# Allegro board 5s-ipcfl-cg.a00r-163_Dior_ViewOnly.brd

Outline 170 x 172.3 mm; copper layers: TOP, GND, IN1, IN2, VCC, BOTTOM. Coordinates in mm from the lower left corner of the outline.
Outline path: 0,171.3 arc(0.29,172.01) 1,172.3 17.66,172.3 17.66,158.82 arc(18.16,158.32) 18.66,158.82 33.56,158.82 arc(34.06,158.32) 34.56,158.82 34.56,172.3 169,172.3 arc(169.71,172.01) 170,171.3 170,13.3 arc(169.71,12.59) 169,12.3 160,12.3 arc(159.29,12.01) 159,11.3 159,9.3 arc(158.71,8.59) 158,8.3 142.76,8.3 arc(141.82,8.21) 140.91,7.94 137.69,6.66 arc(136.78,6.39) 135.84,6.3 110,6.3 arc(109.65,6.45) 109.5,6.8 109.5,7.8 arc(109.35,8.15) 109,8.3 101,8.3 arc(100.65,8.15) 100.5,7.8 100.5,6.8 arc(100.35,6.45) 100,6.3 74.8,6.3 arc(74.45,6.15) 74.3,5.8 74.3,4.8 arc(74.15,4.45) 73.8,4.3 66.3,4.3 arc(65.59,4.01) 65.3,3.3 65.3,1 arc(65.01,0.29) 64.3,0 25.6,0 arc(24.89,0.29) 24.6,1 24.6,4.8 arc(24.31,5.51) 23.6,5.8 20.2,5.8 arc(19.49,6.09) 19.2,6.8 19.2,10.8 arc(18.91,11.51) 18.2,11.8 8,11.8 arc(7.29,11.51) 7,10.8 arc(6.85,10.45) 6.5,10.3 1,10.3 arc(0.29,10.59) 0,11.3 0,171.3

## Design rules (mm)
net group CLK_REQ: nets LAN_CLKREQ#_R LANCLK_REQ_N
net group HDA: nets HDA_SDI0 HDA_SDI0_R
net group SMB: nets SMLI_DATA SMLI_DATA_R
net group ASY: nets H_THMTRIP# H_THMTRIP#_CPU H_TRIGIN PCH_TGR_L900MIL PCH_THMTRIP#_R
net group DP: nets DPC_AUXN DPC_AUXN_C DPC_AUXP DPC_AUXP_C
net group DP_CTRL: nets DPC_CTRL_CLK DPC_CTRL_CLK_R DPC_CTRL_DATA DPC_CTRL_DATA_R
net group SVID: nets VCORE_ALERT VCORE_SCLK VCORE_SDIO VIDALERT# VIDSCLK VIDSOUT
net group USB2.0: nets USB_PN2_F2 USB_PN2_F2_R USB_PP1_F1 USB_PP1_F1_R USB_PP2_F2 USB_PP2_F2_R

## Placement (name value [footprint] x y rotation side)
AC1  22PF/50V  [MX_C0402_SMALL_T01]  18.55 26.92 225 top
AC3  10UF/6.3V  [MX_C0603_SMALL_T01]  20.68 26.84 0 top
AC4  0.1UF/6.3V  [TX_C0201]  20.62 25.8 0 top
AC5  0.1UF/16V  [MX_C0402_SMALL_T01]  23.53 26.69 270 bottom
AC6  0.1UF/25V  [MX_C0402_SMALL_T01]  35.24 110.5 270 bottom
AC12  10UF/6.3V  [MX_C0603_SMALL_T01]  14.82 16.14 270 top
AC13  0.1UF/16V  [MX_C0402_SMALL_T01]  14.88 17.8 180 top
AC14  1UF/16V  [MX_C0603_SMALL_T01]  22.02 18.68 0 top
AC20  10PF/50V  [MX_C0402_SMALL_T01]  25.68 109.97 0 top
AC24  1UF/16V  [MX_C0603_SMALL_T01]  22.03 17.24 0 top
AC25  10PF/50V  [MX_C0402_SMALL_T01]  25.68 109.04 0 top
AC47  10PF/50V  [MX_C0402_SMALL_T01]  5.93 98.11 180 bottom
AC52  10UF/6.3V  [MX_C0603_SMALL_T01]  24.62 26.77 270 bottom
AC53  1UF/6.3V  [MX_C0402_SMALL_T01]  22.93 21.11 90 bottom
AC70  22PF/50V  [MX_C0402_SMALL_T01]  42.31 110.53 90 top
AC82  10UF/6.3V  [MX_C0603_SMALL_T01]  22.09 25.96 90 bottom
AC84  0.1UF/16V  [MX_C0402_SMALL_T01]  7.65 26.96 0 top
AC85  10UF/6.3V  [MX_C0603_SMALL_T01]  11.41 22.09 180 top
AC86  10UF/6.3V  [MX_C0603_SMALL_T01]  16.11 16.23 270 top
AC87  2.2UF/6.3V  [MX_C0603_SMALL_T01]  17.38 16.25 270 top
AC88  10UF/6.3V  [MX_C0603_SMALL_T01]  22.03 18.69 0 bottom
AC89  10UF/6.3V  [MX_C0603_SMALL_T01]  24.05 18.81 270 bottom
AC90  10UF/6.3V  [MX_C0603_SMALL_T01]  24.76 19.42 270 top
AC92  10UF/6.3V  [MX_C0603_SMALL_T01]  24.12 29.95 90 top
AC93  0.1UF/16V  [MX_C0402_SMALL_T01]  23.14 21.43 0 top
AC94  0.1UF/16V  [MX_C0402_SMALL_T01]  24.28 27.24 270 top
AC95  10UF/6.3V  [MX_C0603_SMALL_T01]  23.22 25.02 0 top
AC96  0.1UF/16V  [MX_C0402_SMALL_T01]  23.16 23.1 0 top
AC97  0.1UF/16V  [MX_C0402_SMALL_T01]  12.56 23.34 180 top
AC98  0.1UF/16V  [MX_C0402_SMALL_T01]  12.53 24.25 180 top
AC99  10UF/16V  [MX_C0805_SMALL_T02]  9.04 18 90 top
AC100  10UF/16V  [MX_C0805_SMALL_T02]  11.13 20.44 0 top
AC202  22UF/16V  [MX_C1206_H75]  11.92 18.22 180 top
AC203  22UF/16V  [MX_C1206_H75]  11.92 15.74 180 top
AC204  100PF/50V  [MX_C0402_SMALL_T01]  6.94 25.09 180 top
AC205  0.1UF/16V  [MX_C0402_SMALL_T01]  9.6 25.22 0 top
AC206  0.1UF/16V  [MX_C0402_SMALL_T01]  4.73 27.68 270 top
AC207  47UF/6.3V  [TX_C0805_T02_H57]  110.47 162.81 270 top
AC208  10UF/16V  [MX_C0805_SMALL_T02]  43.86 137.84 0 bottom
AC209  0.1UF/25V  [MX_C0402_SMALL_T01]  44.27 133.47 270 bottom
AMB_Q1  2N3904G-TF  [DX_TO92_102_FSBREC_LF5]  156.33 16.6 0 top
APD1  1N4148WX  [TX_SOD323_79X55_H45]  58.86 47.72 90 top
APD2  1N4148WX  [TX_SOD323_79X55_H45]  58.69 52.12 270 top
APR5  0 Ohm  [MX_R0402_SMALL_T01]  34.77 47.05 135 top
APR6  0 Ohm  [MX_R0402_SMALL_T01]  41.93 55.26 0 bottom
APR7  0 Ohm  [MX_R0402_SMALL_T01]  30.96 43.78 180 bottom
APR8  0 Ohm  [MX_R0402_SMALL_T01]  46.35 55.73 0 bottom
APR9  0 Ohm  [MX_R0402_SMALL_T01]  57.2 53.63 90 bottom
APR10  0 Ohm  [MX_R0402_SMALL_T01]  47.98 55.84 270 bottom
APR17  0Ohm  [MX_R0402_SHORT_SMALL_T01]  11.5 106.44 180 top
APR18  0Ohm  [MX_R0402_SHORT_SMALL_T01]  18.56 104.31 0 top
APR19  0Ohm  [MX_R0402_SHORT_SMALL_T01]  18.86 118.53 90 top
APR29  0Ohm  [MX_R0402_SHORT_SMALL_T01]  45.48 47.77 90 top
APR30  0Ohm  [MX_R0402_SHORT_SMALL_T01]  44.56 47.77 90 top
APR31  0Ohm  [MX_R0402_SHORT_SMALL_T01]  43.64 47.77 90 top
APR46  0  [MX_R0402_SMALL_T01]  6.31 20.14 270 top
APR47  0Ohm  [MX_R0402_SHORT_SMALL_T01]  5.39 20.19 270 top
APR75  0Ohm  [MX_R0402_SHORT_SMALL_T01]  51.61 61.84 180 bottom
APR112  0Ohm  [MX_R0402_SHORT_SMALL_T01]  27.71 109.69 270 top
APR115  0 Ohm  [MX_R0402_SMALL_T01]  58.55 44.49 90 top
APR116  0Ohm  [MX_R0402_SHORT_SMALL_T01]  57.12 44.52 0 top
APR117  0 Ohm  [MX_R0402_SMALL_T01]  7.05 113.23 180 bottom
APR119  0 Ohm  [MX_R0402_SMALL_T01]  18.33 105.26 0 top
APR120  0  [MX_R0402_SMALL_T01]  58.8 57.42 90 top
APR121  0Ohm  [MX_R0402_SHORT_SMALL_T01]  58.95 56 0 top
APR122  0Ohm  [MX_R0402_SHORT_SMALL_T01]  7.05 114.2 0 bottom
APR123  0Ohm  [MX_R0402_SHORT_SMALL_T01]  56.82 47.49 180 top
APR124  0  [MX_R0402_SMALL_T01]  56.82 46.55 180 top
APR125  0 Ohm  [MX_R0402_SMALL_T01]  15.85 104.46 0 top
APR126  0 Ohm  [MX_R0402_SMALL_T01]  15.94 105.39 0 top
APR127  0 Ohm  [MX_R0402_SMALL_T01]  26.44 45.3 90 bottom
APR128  0 Ohm  [MX_R0402_SMALL_T01]  27.38 45.3 90 bottom
APR129  0Ohm  [MX_R0402_SHORT_SMALL_T01]  136.64 41.4 270 bottom
APR130  0 Ohm  [MX_R0402_SMALL_T01]  135.62 41.4 90 bottom
APR131  0 Ohm  [MX_R0402_SMALL_T01]  138.16 42.24 180 bottom
APR132  0  [MX_R0402_SMALL_T01]  50.48 49.88 180 top
APR133  0  [MX_R0402_SMALL_T01]  50.48 48.76 180 top
APR134  0  [MX_R0402_SMALL_T01]  34.26 57.8 0 bottom
APR135  0  [MX_R0402_SMALL_T01]  51.61 60.92 180 bottom
APR136  10K  [MX_R0402_SMALL_T01]  56.83 50.87 0 top
APR137  10K  [MX_R0402_SMALL_T01]  57.11 49.37 180 top
APR142  0  [MX_R0402_SMALL_T01]  13.98 102.42 180 top
APR143  0  [MX_R0402_SMALL_T01]  14.29 103.41 180 top
APR144  0  [MX_R0402_SMALL_T01]  14.25 105.27 90 top
AQ2  NX7002AK  [TX_SOT23_2D4_T01_H43]  31.62 16.14 270 top
AQ3  NX7002AK  [TX_SOT23_2D4_T01_H43]  27.3 16.16 270 top
AQ17  SSM6N15FU  [TX_SOIC_6P_26_87X53_COLY]  106.56 169.27 270 bottom
AQ18  SSM6N15FU  [TX_SOIC_6P_26_87X53_COLY]  109.07 168.9 90 top
AQ19  SSM6N15FU  [TX_SOIC_6P_26_87X53_COLY]  111.54 159.23 90 top
AQ20  SSM6N15FU  [TX_SOIC_6P_26_87X53_COLY]  69.82 138.55 0 top
AR14  75  [MX_R0402_SMALL_T01]  39.28 15.01 270 top
AR15  75  [MX_R0402_SMALL_T01]  43.23 16.58 0 top
AR17  100KOHM  [MX_R0402_SMALL_T01]  32.15 18.71 270 top
AR19  1K  [MX_R0402_SMALL_T01]  26.64 17.63 270 bottom
AR22  18.2 OHM  [MX_R0402_SMALL_T01]  23.56 15.08 0 top
AR23  18.2 OHM  [MX_R0402_SMALL_T01]  24.06 16.35 90 top
AR29  100KOHM  [MX_R0402_SMALL_T01]  27.58 17.63 270 bottom
AR30  70Ohm/100Mhz  [MX_L0603]  166.75 46.14 270 bottom
AR31  70Ohm/100Mhz  [MX_L0603]  164.97 46.09 270 bottom
AR36  0Ohm  [MX_R0603_SHORT_SMALL_T01]  27.18 20.69 180 bottom
AR38  0  [MX_R0603_SMALL_T01]  27.18 19.19 180 bottom
AR40  0  [MX_R0603_SMALL_T01]  22.92 30.02 90 top
AR41  1K  [MX_R0402_SMALL_T01]  82.87 120.77 180 bottom
AR43  1K  [MX_R0402_SMALL_T01]  75.94 117.34 0 top
C1  0.01UF/50V  [MX_C0402_SMALL_T01]  23.44 105.94 270 top
C2  0.01UF/50V  [MX_C0402_SMALL_T01]  22.16 105.94 270 top
C3  0.1UF/16V  [MX_C0402_SMALL_T01]  25.69 111.81 0 top
C4  10UF/6.3V  [MX_C0603_SMALL_T01]  25.72 114.11 0 top
C5  0.01UF/50V  [MX_C0402_SMALL_T01]  25.68 110.89 0 top
C6  0.1UF/16V  [MX_C0402_SMALL_T01]  25.68 108.12 0 top
C7  10UF/6.3V  [MX_C0603_SMALL_T01]  25.72 115.33 0 top
C8  0.01UF/50V  [MX_C0402_SMALL_T01]  4.24 106.44 0 top
C9  0.01UF/50V  [MX_C0402_SMALL_T01]  6.02 106.44 180 top
C10  0.1UF/16V  [MX_C0402_SMALL_T01]  8.3 106.44 0 top
C11  10UF/6.3V  [MX_C0603_SMALL_T01]  25.72 112.89 0 top
C12  180PF/50V  [MX_C0402_SMALL_T01]  15.94 106.33 180 top
C15  120PF/50V  [MX_C0402_SMALL_T01]  33.13 83.07 180 bottom
C16  120PF/50V  [MX_C0402_SMALL_T01]  33.02 83.98 0 bottom
C17  47PF/50V  [MX_C0402_SMALL_T01]  33.29 84.92 0 bottom
C18  120PF/50V  [MX_C0402_SMALL_T01]  33.18 85.87 180 bottom
C45  0.1UF/16V  [MX_C0402_SMALL_T01]  50.87 133.64 0 bottom
C49  1UF/16V  [MX_C0603_SMALL_T01]  20.22 150 180 top
C81  180PF/50V  [MX_C0402_SMALL_T01]  19.76 111.24 90 bottom
C82  180PF/50V  [MX_C0402_SMALL_T01]  20.99 113.5 270 bottom
C83  47PF/50V  [MX_C0402_SMALL_T01]  75.36 140.86 270 bottom
C85  4.7UF/6.3V  [TX_C0402_H24]  25.49 111.66 0 bottom
C86  4.7UF/6.3V  [MX_C0603_SMALL_T01]  36.14 103.16 90 bottom
C94  1000PF/50V  [MX_C0402_SMALL_T01]  112.63 42.29 270 bottom
C97  1UF/16V  [MX_C0603_SMALL_T01]  18.01 148.83 180 top
C98  1UF/16V  [MX_C0603_SMALL_T01]  18.01 147.56 180 top
C178  100uF/16V  [DX_CE_98_268_H236_HD31_LF5]  161.66 78.3 270 top
C200  0.1UF/16V  [MX_C0402_SMALL_T01]  39.57 100.27 0 bottom
C201  10PF/50V  [MX_C0402_SMALL_T01]  73.94 18.1 0 top
C202  10PF/50V  [MX_C0402_SMALL_T01]  82.94 152.82 0 bottom
C204  10PF/50V  [MX_C0402_SMALL_T01]  111.81 162.22 270 top
C205  10PF/50V  [MX_C0402_SMALL_T01]  122.81 141.16 90 top
C206  10PF/50V  [MX_C0402_SMALL_T01]  121.84 141.16 90 top
C207  10PF/50V  [MX_C0402_SMALL_T01]  113.13 142.1 90 top
C248  0.1UF/16V  [MX_C0402_SMALL_T01]  13.94 13.3 180 top
C249  0.1UF/16V  [MX_C0402_SMALL_T01]  16.18 13.53 180 top
C258  1UF/6.3V  [MX_C0402_SMALL_T01]  165.94 50.76 180 bottom
C306  10PF/50V  [MX_C0402_SMALL_T01]  50.87 134.56 0 bottom
C316  10PF/50V  [MX_C0402_SMALL_T01]  30.3 48.5 270 top
C2715  1UF/6.3V  [TX_C0201_T009_H14]  31.76 72.36 45 top
C2726  0.1UF/16V  [MX_C0402_SMALL_T01]  32.36 70.98 270 top
C3101  100PF/50V  [MX_C0402_SMALL_T01]  36.24 168.68 270 top
C3102  100PF/50V  [MX_C0402_SMALL_T01]  16 168.63 270 top
C3907  0.1UF/16V  [MX_C0402_SMALL_T01]  42.26 170.17 90 top
C4000  1UF/6.3V  [TX_C0201_T009_H14]  17.47 144.03 180 top
C4001  0.1UF/16V  [MX_C0402_SMALL_T01]  17.04 137.27 0 top
C4002  0.1UF/16V  [MX_C0402_SMALL_T01]  21.31 137.66 180 top
C4003  4.7UF/6.3V  [MX_C0402_SMALL_T015]  17.52 143.2 180 top
C4004  4.7UF/6.3V  [MX_C0402_SMALL_T015]  15.34 137.15 90 bottom
C4005  4.7UF/6.3V  [MX_C0402_SMALL_T015]  15.34 135.5 270 bottom
C4006  0.1UF/16V  [MX_C0402_SMALL_T01]  19.96 136.08 90 top
C4007  0.1UF/16V  [MX_C0402_SMALL_T01]  18.39 140.43 270 top
C4008  0.1UF/16V  [MX_C0402_SMALL_T01]  17.45 140.43 270 top
C4009  0.1UF/16V  [MX_C0402_SMALL_T01]  19.05 136.01 90 top
C4010  0.1UF/16V  [MX_C0402_SMALL_T01]  21.31 138.67 180 top
C4011  0.1UF/16V  [MX_C0402_SMALL_T01]  20.9 136.08 90 top
C4012  1UF/6.3V  [TX_C0201_T009_H14]  23.39 134.08 0 top
C4013  1UF/16V  [MX_C0603_SMALL_T02_H37]  17.61 138.39 0 top
C4014  0.1UF/16V  [MX_C0402_SMALL_T01]  19.3 140.43 270 top
C4015  0.1UF/16V  [MX_C0402_SMALL_T01]  18.13 136.01 90 top
C4016  4.7UF/6.3V  [MX_C0402_SMALL_T015]  22.17 140.02 270 top
C4017  0.1UF/16V  [MX_C0402_SMALL_T01]  21.22 140.02 270 top
C4018  0.1UF/16V  [MX_C0402_SMALL_T01]  17.14 142.39 270 bottom
C4019  0.1UF/16V  [MX_C0402_SMALL_T01]  18.06 142.39 270 bottom
C4020  0.1UF/16V  [MX_C0402_SMALL_T01]  15.31 142.05 270 bottom
C4021  0.1UF/16V  [MX_C0402_SMALL_T01]  16.23 142.05 270 bottom
C4022  12PF/50V  [MX_C0402_SMALL_T01]  24.74 136.39 90 bottom
C4023  12PF/50V  [MX_C0402_SMALL_T01]  23.85 138.17 270 bottom
C4024  10PF/50V  [MX_C0402_SMALL_T01]  19.05 144.41 90 bottom
C4301  470PF/50V  [MX_C0402_SMALL_T01]  44.37 14.34 0 top
C4302  470PF/50V  [MX_C0402_SMALL_T01]  41.48 13.43 270 top
C4303  680PF/50V  [MX_C0402_SMALL_T01]  31.04 12.54 0 top
C4304  680PF/50V  [MX_C0402_SMALL_T01]  37.37 14.32 180 top
C4305  470PF/50V  [MX_C0402_SMALL_T01]  25.64 14.16 0 top
C4306  470PF/50V  [MX_C0402_SMALL_T01]  33.86 13.58 90 top
C4307  680PF/50V  [MX_C0402_SMALL_T01]  44.88 15.28 0 top
C4308  680PF/50V  [MX_C0402_SMALL_T01]  39.83 16.42 180 top
C4309  680PF/50V  [MX_C0402_SMALL_T01]  33.09 17.58 90 top
C4310  680PF/50V  [MX_C0402_SMALL_T01]  37.02 17.08 0 top
C7201  10UF/6.3V  [MX_C0603_SMALL_T01]  8.41 63.57 270 bottom
C7202  10UF/6.3V  [MX_C0603_SMALL_T01]  16.41 63.39 0 bottom
C7203  10PF/50V  [MX_C0402_SMALL_T01]  9.29 69.64 180 bottom
C7204  0.1UF/16V  [MX_C0402_SMALL_T01]  9.4 68.49 180 bottom
C7205  0.1UF/6.3V  [TX_C0201]  12.04 62.63 0 bottom
C7206  0.1UF/6.3V  [TX_C0201]  18.95 69.43 0 bottom
C7207  0.1UF/6.3V  [TX_C0201]  18.95 70.09 0 bottom
C7208  0.1UF/16V  [MX_C0402_SMALL_T01]  7.14 67.63 180 bottom
C7209  4.7UF/6.3V  [TX_C0402_H24]  15.45 71.97 0 bottom
C7210  0.01UF/50V  [MX_C0402_SMALL_T01]  15.44 71.03 0 bottom
C8301  0.1UF/16V  [MX_C0402_SMALL_T01]  3.21 46.44 270 bottom
C8302  0.1UF/16V  [MX_C0402_SMALL_T01]  4.39 129.05 0 bottom
C8303  0.1UF/16V  [MX_C0402_SMALL_T01]  4.43 72.39 0 bottom
C8304  0.1UF/16V  [MX_C0402_SMALL_T01]  4.6 46.42 270 bottom
C8305  0.1UF/16V  [MX_C0402_SMALL_T01]  89.19 23.4 90 bottom
C8306  0.1UF/16V  [MX_C0402_SMALL_T01]  90.23 23.4 90 bottom
C8307  0.1UF/16V  [MX_C0402_SMALL_T01]  90.92 16.08 270 bottom
C8308  0.1UF/16V  [MX_C0402_SMALL_T01]  75.31 27.73 0 top
C8309  0.1UF/16V  [MX_C0402_SMALL_T01]  125.2 106.01 90 bottom
C8310  0.1UF/16V  [MX_C0402_SMALL_T01]  92.91 76.72 180 bottom
C8311  0.1UF/16V  [MX_C0402_SMALL_T01]  146.91 86.12 0 bottom
C8312  0.1UF/16V  [MX_C0402_SMALL_T01]  116.76 105.98 90 bottom
C8313  0.1UF/16V  [MX_C0402_SMALL_T01]  60.09 105.81 90 bottom
C8314  0.1UF/16V  [MX_C0402_SMALL_T01]  52.22 88.7 270 bottom
C8315  0.1UF/16V  [MX_C0402_SMALL_T01]  54.71 94.63 270 bottom
C8316  10UF/16V  [MX_C0805_SMALL_T02]  54.99 22.72 0 bottom
C9478  1UF/6.3V  [MX_C0402_SMALL_T01]  2.79 148.53 180 bottom
C941488  0.1UF/16V  [MX_C0402_SMALL_T01]  29.74 33.14 270 top
C941489  0.1UF/16V  [MX_C0402_SMALL_T01]  28.98 31.71 0 top
C941490  22UF/6.3V  [MX_C0603_SMALL_T02]  95.36 28.32 90 bottom
C941491  22UF/6.3V  [MX_C0603_SMALL_T02]  96.68 28.32 90 bottom
C941492  10PF/50V  [MX_C0402_SMALL_T01]  7.62 20.41 180 top
C941623  22UF/6.3V  [MX_C0603_SMALL_T02]  157.14 168.39 0 top
C941625  0.1UF/16V  [MX_C0402_SMALL_T01]  132.94 166.49 180 top
C941629  1UF/25V  [MX_C0603_SMALL_T01]  156.87 170.68 0 top
C941631  22UF/6.3V  [MX_C0603_SMALL_T02]  113.02 117.98 0 bottom
C941632  22UF/6.3V  [MX_C0603_SMALL_T02]  113.04 116.66 0 bottom
C941633  22UF/6.3V  [MX_C0603_SMALL_T02]  114.66 115.82 0 top
C941634  22UF/6.3V  [MX_C0603_SMALL_T02]  114.66 114.42 0 top
C941635  0.1UF/16V  [MX_C0402_SMALL_T01]  65.21 44.52 180 bottom
C941636  0.1UF/16V  [MX_C0402_SMALL_T01]  66.27 48.17 0 top
C941643  4.7UF/6.3V  [MX_C0603_SMALL_T01]  42.77 98.3 180 bottom
C941644  4.7UF/6.3V  [MX_C0603_SMALL_T01]  49.08 95.16 90 bottom
C941645  22UF/6.3V  [MX_C0603_SMALL_T02]  104.65 166.89 0 top
C941646  10PF/50V  [MX_C0402_SMALL_T01]  71.93 17.1 180 top
C941647  10PF/50V  [MX_C0402_SMALL_T01]  49.76 17.01 180 top
C941648  0.47UF/16V  [TX_C0603_T015_H37]  30.78 38.24 180 top
C941649  0.47UF/16V  [TX_C0603_T015_H37]  29.08 23.84 180 top
CB171  10UF/25V  [MX_C0805_SMALL_T02]  161.29 72.89 180 top
CB4132  1000PF/50V  [MX_C0402_SMALL_T01]  131.33 61.68 0 bottom
CB4133  0.1UF/16V  [MX_C0402_SMALL_T01]  48.11 72.31 0 top
CB4134  0.1UF/16V  [MX_C0402_SMALL_T01]  48.11 73.23 0 top
CB4135  0.1UF/16V  [MX_C0402_SMALL_T01]  87.11 125.83 180 bottom
CB4152  0.1UF/16V  [MX_C0402_SMALL_T01]  2.84 131.33 180 top
CM3101  90Ohm/100Mhz  [MX_CHOKE_4P_79X47_FUK_COLAY]  7.88 126.39 270 top
CM3102  90Ohm/100Mhz  [MX_CHOKE_4P_79X47_FUK_COLAY]  10.12 127 270 top
CM3103  90Ohm/100Mhz  [MX_CHOKE_4P_79X47_FUK_COLAY]  12.35 127 270 top
CM3104  90Ohm/100Mhz  [MX_CHOKE_4P_79X47_FUK_COLAY]  14.61 127 270 top
CM3301  12ohm  [TX_CHOKE_4P_35X28_PAN]  78.08 20.31 0 top
CM3302  12ohm  [TX_CHOKE_4P_35X28_PAN]  79.86 20.31 0 top
CM3303  90ohm  [MX_CHOKE_4P_55X47_CHI]  69.45 18.54 270 top
CM3601  12ohm  [TX_CHOKE_4P_35X28_PAN]  69.78 148.8 0 bottom
CM3602  12ohm  [TX_CHOKE_4P_35X28_PAN]  71.66 148.21 0 bottom
CM3603  90ohm  [MX_CHOKE_4P_55X47_CHI]  62.36 161.56 90 top
CM3604  90ohm  [MX_CHOKE_4P_55X47_CHI]  60.81 161.55 90 top
CM3605  12ohm  [TX_CHOKE_4P_35X28_PAN]  70.04 150.84 180 top
CM3606  12ohm  [TX_CHOKE_4P_35X28_PAN]  71.9 150.9 180 top
CM3703  90ohm  [MX_CHOKE_4P_55X47_CHI]  40.72 153.73 90 top
CM3704  90ohm  [MX_CHOKE_4P_55X47_CHI]  42.25 153.73 90 top
CM4003  90ohm  [MX_CHOKE_4P_55X47_CHI]  67.8 18.55 270 top
CM4004  12ohm  [TX_CHOKE_4P_35X28_PAN]  63.47 20.28 0 top
CM4005  12ohm  [TX_CHOKE_4P_35X28_PAN]  65.12 20.18 0 top
CR1  GREEN  [MX_LED_2P_63X31_H16]  167.14 23.21 180 top
CR2  GREEN  [MX_LED_2P_63X31_H16]  167.14 24.74 180 top
CR4  CR6  [MX_LED_2P_63X31_EVER]  167.14 30.81 180 top
CR5  GREEN  [MX_LED_2P_63X31_H16]  167.14 29.28 180 top
CR6  GREEN  [MX_LED_2P_63X31_H16]  167.14 27.76 180 top
CR7  GREEN  [MX_LED_2P_63X31_H16]  167.14 32.33 180 top
CR15  WHITE  [DX_LED_D_2P_90_1H_RA_CO_LF5]  21.75 9.1 0 top
CR22  GREEN  [MX_LED_2P_63X31_H16]  167.14 26.26 180 top
CR23  GREEN  [MX_LED_2P_63X31_H16]  167.12 34.29 180 top
D3  BAT54CW  [MX_SOT323]  23.94 148.59 270 top
D4C1  10PF/50V  [MX_C0402_SMALL_T01]  85.18 67.33 180 top
D4C2  1UF/6.3V  [TX_C0201_T009_H14]  85.18 66.37 180 top
D4C3  1UF/6.3V  [TX_C0201_T009_H14]  85.18 65.06 180 top
D4C4  1UF/6.3V  [TX_C0201_T009_H14]  88.48 72.31 90 top
D4C5  0.1UF/16V  [MX_C0402_SMALL_T01]  132.6 61.26 270 bottom
D4C6  2.2UF/6.3V  [MX_C0603_SMALL_T01]  90.06 73.17 180 top
D4C7  0.1UF/16V  [MX_C0402_SMALL_T01]  92.57 72.01 0 top
D4C8  10PF/50V  [MX_C0402_SMALL_T01]  90.31 72.01 180 top
D4C9  0.1UF/6.3V  [MX_C0201]  120.57 59.15 90 bottom
D4C10  22UF/6.3V  [MX_C0603_SMALL_T02]  114.56 62.28 0 bottom
D4C11  0.1UF/16V  [MX_C0402_SMALL_T01]  114.31 63.4 0 bottom
D4C12  10PF/50V  [MX_C0402_SMALL_T01]  92.77 49.53 0 bottom
D4C13  1UF/6.3V  [TX_C0201_T009_H14]  92.26 46.99 0 bottom
D4C14  1UF/6.3V  [TX_C0201_T009_H14]  92.77 48.59 0 bottom
D4C15  1UF/6.3V  [TX_C0201_T009_H14]  91.68 57.27 90 bottom
D4C16  0.1UF/16V  [MX_C0402_SMALL_T01]  131.75 46.9 0 bottom
D4C17  2.2UF/6.3V  [MX_C0603_SMALL_T01]  93.61 60.69 0 bottom
D4C18  0.1UF/16V  [MX_C0402_SMALL_T01]  93 61.76 0 bottom
D4C19  10PF/50V  [MX_C0402_SMALL_T01]  93.3 65.78 0 bottom
D4C20  0.1UF/6.3V  [MX_C0201]  120.51 49.62 0 bottom
D4C21  22UF/6.3V  [MX_C0603_SMALL_T02]  115.19 48.99 270 bottom
D4C22  0.1UF/16V  [MX_C0402_SMALL_T01]  117.27 48.88 270 bottom
D4C23  1UF/6.3V  [MX_C0402_SMALL_T01]  114.31 64.39 180 bottom
D4C24  1UF/6.3V  [MX_C0402_SMALL_T01]  116.33 48.88 90 bottom
D4C25  0.1UF/16V  [MX_C0402_SMALL_T01]  118.21 48.88 270 bottom
D4C26  10PF/50V  [MX_C0402_SMALL_T01]  127.82 69.8 0 bottom
D4C27  10PF/50V  [MX_C0402_SMALL_T01]  117.07 57.7 270 bottom
D4C28  10PF/50V  [MX_C0402_SMALL_T01]  63.68 151.27 0 bottom
D4C29  10PF/50V  [MX_C0402_SMALL_T01]  43.2 170.17 90 top
D4C31  10PF/50V  [MX_C0402_SMALL_T01]  119.02 72.56 90 top
D4C32  10PF/50V  [MX_C0402_SMALL_T01]  132.26 49.7 180 bottom
D4C33  0.1UF/16V  [MX_C0402_SMALL_T01]  120.51 47.79 0 bottom
D4C34  0.1UF/16V  [MX_C0402_SMALL_T01]  114.4 59.81 270 bottom
D4CB1  0.1UF/6.3V  [MX_C0201]  117.7 72.13 180 top
D4CB2  0.1UF/6.3V  [MX_C0201]  128.01 72.22 90 top
D4CB3  0.1UF/6.3V  [MX_C0201]  123.21 72.3 180 top
D4CB4  0.1UF/6.3V  [MX_C0201]  130.37 72.21 90 top
D4CB5  0.1UF/6.3V  [MX_C0201]  120.62 66.28 270 bottom
D4CB6  0.1UF/6.3V  [MX_C0201]  109.27 57.22 270 bottom
D4CB7  0.1UF/6.3V  [MX_C0201]  111.12 61.39 90 bottom
D4CB8  0.1UF/6.3V  [MX_C0201]  143.74 60.57 180 bottom
D4CB9  0.1UF/6.3V  [MX_C0201]  112.13 48.89 270 bottom
D4CB10  0.1UF/6.3V  [MX_C0201]  107.23 58.25 90 bottom
D4CB11  0.1UF/6.3V  [MX_C0201]  134.59 49.44 90 bottom
D4CB12  0.1UF/6.3V  [MX_C0201]  127.54 57.1 270 bottom
D4CB13  0.1UF/6.3V  [MX_C0201]  139.04 57.29 90 bottom
D4CB14  0.1UF/6.3V  [MX_C0201]  126.49 59.5 90 bottom
D4CB15  0.1UF/6.3V  [MX_C0201]  121.65 59.15 90 bottom
D4CB16  10PF/50V  [MX_C0402_SMALL_T01]  145.13 49.15 90 bottom
D4CB17  22UF/6.3V  [MX_C0603_SMALL_T02]  100.29 60.68 180 bottom
D4CB18  22UF/6.3V  [MX_C0603_SMALL_T02]  95.03 69.31 180 bottom
D4CB19  22UF/6.3V  [MX_C0603_SMALL_T02]  155.34 61.25 270 bottom
D4CB20  22UF/6.3V  [MX_C0603_SMALL_T02]  150.11 66.56 90 bottom
D4CB21  22UF/6.3V  [MX_C0603_SMALL_T02]  154.13 47.74 270 bottom
D4CB22  22UF/6.3V  [MX_C0603_SMALL_T02]  96.8 57.67 0 bottom
D4CB23  22UF/6.3V  [MX_C0603_SMALL_T02]  100.3 49.4 180 bottom
D4CB24  22UF/6.3V  [MX_C0603_SMALL_T02]  149.66 56.78 270 bottom
D4CE1  220UF/2V  [MX_C7343D_H79]  118.21 74.64 0 bottom
D4CE2  220UF/2V  [MX_C7343D_H79]  126.32 48.61 180 bottom
D4R2  240  [MX_R0402_SMALL_T01]  124.57 61.08 270 bottom
D4R5  0  [MX_R0402_SMALL_T01]  85.18 70.49 0 top
D4R6  0  [MX_R0402_SMALL_T01]  85.18 69.57 0 top
D4R7  0  [MX_R0402_SMALL_T01]  112.18 61.31 90 bottom
D4R8  1K  [MX_R0402_SMALL_T01]  116.54 60.61 180 bottom
D4R9  1K  [MX_R0402_SMALL_T01]  116.54 61.53 0 bottom
D4R10  0Ohm  [MX_R0402_SHORT_SMALL_T01]  85.18 71.41 180 top
D4R11  0Ohm  [MX_R0402_SHORT_SMALL_T01]  85.18 68.63 180 top
D4R12  0Ohm  [MX_R0402_SHORT_SMALL_T01]  112.52 65.06 90 bottom
D4R14  240  [MX_R0402_SMALL_T01]  123.87 51.99 0 bottom
D4R16  0  [MX_R0402_SMALL_T01]  92.18 51.96 270 bottom
D4R17  0Ohm  [MX_R0402_SHORT_SMALL_T01]  90.64 51.56 270 bottom
D4R18  0  [MX_R0402_SMALL_T01]  113.14 48.8 90 bottom
D4R19  1K  [MX_R0402_SMALL_T01]  120.51 48.7 180 bottom
D4R20  1K  [MX_R0402_SMALL_T01]  120.51 46.75 0 bottom
D4R21  0Ohm  [MX_R0402_SHORT_SMALL_T01]  91.34 49.25 270 bottom
D4R22  0  [MX_R0402_SMALL_T01]  90.42 49.25 270 bottom
D4R23  0Ohm  [MX_R0402_SHORT_SMALL_T01]  114.07 48.8 270 bottom
D4T1  TPC26T  [MX_TPC26T_S4_68]  114.3 71.8 0 top
D4T2  TPC26T  [MX_TPC26T_S4_68]  116.94 63.11 180 bottom
D4T3  TPC26T  [MX_TPC26T_S4_68]  114.68 53.15 180 bottom
D4T4  TPC26T  [MX_TPC26T_S4_68]  114.65 51.4 180 bottom
D519  AZ5125-01J  [MX_S0402_AMAZ_COLAY_T01]  7.31 14.59 0 top
D521  BAV99W-L  [MX_SOT323]  108.02 38.97 270 bottom
D522  BAT54CW  [MX_SOT323]  33.14 47.74 90 bottom
D524  BAT54AW  [MX_SOT323]  68.05 53.3 90 top
D525  BAT54CW  [MX_SOT323]  24.4 151.52 0 top
D3101  AZ3133-08F_R7G  [MX_DFN_10P_118X79_3PAD]  13.67 131.28 180 top
D3102  AZ3133-08F_R7G  [MX_DFN_10P_118X79_3PAD]  9.56 131.28 180 top
D3103  AZ5125-01J  [MX_S0402_AMAZ_COLAY_T01]  35.34 156.59 90 top
D3104  AZ5125-01J  [MX_S0402_AMAZ_COLAY_T01]  36.85 163.97 0 top
D3105  AZ5125-01J  [MX_S0402_AMAZ_COLAY_T01]  16.62 146.79 0 bottom
D3106  AZ5125-01J  [MX_S0402_AMAZ_COLAY_T01]  18.46 150.56 270 top
D3301  IP4284CZ10-TB  [MX_ESD_10P_20_98X39_NXP]  78.98 18.16 0 top
D3302  CM1213_04SO  [MX_SOT23_S6]  68.71 14.85 180 top
D3601  IP4284CZ10-TB  [MX_ESD_10P_20_98X39_NXP]  71.09 150.87 0 bottom
D3602  CM1213_04SO  [MX_SOT23_S6]  61.49 167.68 180 top
D3603  IP4284CZ10-TB  [MX_ESD_10P_20_98X39_NXP]  71.09 153.53 0 top
D3702  CM1213_04SO  [MX_SOT23_S6]  41.63 157.47 0 top
D4003  IP4284CZ10-TB  [MX_ESD_10P_20_98X39_NXP]  64.36 18.07 0 top
D4301  AZ5125-01J  [MX_S0402_AMAZ_COLAY]  44.63 13.25 180 top
D4302  AZ5125-01J  [MX_S0402_AMAZ_COLAY]  39.93 13.25 0 top
D4303  AZ5125-01J  [MX_S0402_AMAZ_COLAY]  35.41 13.6 90 top
D4304  AZ5125-01J  [MX_S0402_AMAZ_COLAY]  29.27 13.57 270 top
D4305  AZ5125-01J  [MX_S0402_AMAZ_COLAY]  37.32 13.28 0 top
D4306  AZ5125-01J  [MX_S0402_AMAZ_COLAY]  25.53 13.08 180 top
D4307  AZ5125-01J  [MX_S0402_AMAZ_COLAY]  32.76 13.35 270 top
D4308  AZ5125-01J  [MX_S0402_AMAZ_COLAY]  27.61 13.08 180 top
D4309  BAT54CW  [MX_SOT323]  29.38 47.35 90 bottom
D4310  AZ5125-01J  [MX_S0402_AMAZ_COLAY_T01]  150.47 157.57 0 top
D5501  AZ5125-01J  [MX_S0402_AMAZ_COLAY]  4.33 23.31 270 bottom
D5502  AZ5125-01J  [MX_S0402_AMAZ_COLAY]  1.67 24.4 90 bottom
D5503  AZ5125-01J  [MX_S0402_AMAZ_COLAY]  2.91 23.28 270 bottom
D6301  TVM1G260M111R  [A_VARISTOR_0603_71X39_TK]  166.9 159.91 0 top
DIMM1  DDR4_SO_260P  [MX_DDR4_260P_20_4HOD_FOX]  124.51 53.18 180 top
DIMM2  DDR4_SO_260P  [MX_DDR4_260P_20_4H_STD_FX]  124.5 65.18 180 top
E16  HEADER_2X5P_K4  [MX_HD_2X5P_79_K4_H248_LF5]  41.25 68.21 90 top
E61  SOCKET_16P  [MX_SOCKET_16P_50_LOTE]  56.44 70.81 270 top
ECR67  0Ohm  [MX_R0402_SHORT_SMALL_T01]  24.93 113.51 270 bottom
ECR73  0Ohm  [MX_R0402_SHORT_SMALL_T01]  25.88 72.48 90 bottom
ECR74  0Ohm  [MX_R0402_SHORT_SMALL_T01]  26.85 72.48 90 bottom
ECR75  0Ohm  [MX_R0402_SHORT_SMALL_T01]  23.93 72.53 90 bottom
ECR76  0Ohm  [MX_R0402_SHORT_SMALL_T01]  24.92 72.48 90 bottom
ECR77  0Ohm  [MX_R0402_SHORT_SMALL_T01]  26.93 91.56 90 top
ECR96  0Ohm  [MX_R0402_SHORT_SMALL_T01]  8.29 95.47 0 top
ECR103  22  [MX_R0402_SMALL_T01]  31.75 89.74 0 bottom
ECR104  0Ohm  [MX_R0402_SHORT_SMALL_T01]  20.45 86.98 90 bottom
ECR106  0  [MX_R0402_SMALL_T01]  26.92 89.93 270 top
ECR107  0  [MX_R0402_SMALL_T01]  24.92 70.6 90 bottom
ECR108  0  [MX_R0402_SMALL_T01]  23.93 70.6 90 bottom
ECR109  0  [MX_R0402_SMALL_T01]  26.85 70.63 90 bottom
ECR110  0  [MX_R0402_SMALL_T01]  25.88 70.6 90 bottom
ECR129  0Ohm  [MX_R0402_SHORT_SMALL_T01]  5.93 101.8 180 bottom
ECR130  0Ohm  [MX_R0402_SHORT_SMALL_T01]  5.93 102.71 180 bottom
ECR131  0Ohm  [MX_R0402_SHORT_SMALL_T01]  6.05 103.63 180 bottom
ECR132  0Ohm  [MX_R0402_SHORT_SMALL_T01]  6.04 105.46 180 bottom
ECR135  0  [MX_R0402_SMALL_T01]  21.94 73.01 0 top
ECR136  0Ohm  [MX_R0402_SHORT_SMALL_T01]  5.93 99.97 180 bottom
ECR137  0Ohm  [MX_R0402_SHORT_SMALL_T01]  5.93 100.89 180 bottom
ECR138  0Ohm  [MX_R0402_SHORT_SMALL_T01]  7.11 89.19 270 top
ECR139  0Ohm  [MX_R0402_SHORT_SMALL_T01]  5.88 89.22 270 top
ECR141  0  [MX_R0402_SMALL_T01]  17.92 118.53 90 top
ECR142  0  [MX_R0402_SMALL_T01]  29.31 103.42 180 bottom
ECR143  0Ohm  [MX_R0402_SHORT_SMALL_T01]  29.31 102.56 180 bottom
ECR144  0Ohm  [MX_R0402_SHORT_SMALL_T01]  29.06 97.5 180 bottom
ECR145  0Ohm  [MX_R0402_SHORT_SMALL_T01]  29.89 96.59 180 bottom
ECR146  0  [MX_R0402_SMALL_T01]  18.01 101.72 180 top
ECR147  0Ohm  [MX_R0402_SHORT_SMALL_T01]  6.92 98.88 180 top
ECR148  0Ohm  [MX_R0402_SHORT_SMALL_T01]  20.05 113.5 270 bottom
ECR149  0Ohm  [MX_R0402_SHORT_SMALL_T01]  23.97 113.51 270 bottom
ECR154  0Ohm  [MX_R0402_SHORT_SMALL_T01]  44.12 40.48 90 top
ECR155  0Ohm  [MX_R0402_SHORT_SMALL_T01]  99.9 12.46 180 bottom
ECR156  0Ohm  [MX_R0402_SMALL_T01]  97.89 8.14 90 top
ECR157  0Ohm  [MX_R0402_SMALL_T01]  99.63 10.02 180 top
ECR159  0  [MX_R0402_SMALL_T01]  41.48 137.63 270 bottom
ECR160  0  [MX_R0402_SMALL_T01]  41.48 136.01 90 bottom
F1  SMD0805P050TF  [TX_POLYSWITCH_2P_87X59_H49]  153.62 165.22 270 top
F3R1  20K  [MX_R0402_SMALL_T01]  64.57 68.54 0 top
F3R2  20K  [MX_R0402_SMALL_T01]  46.23 70.63 90 top
F3R6  0  [MX_R0402_SMALL_T01]  44.68 65.17 180 top
F3R7  33 OHM  [MX_R0402_SMALL_T01]  47.98 66.92 0 top
F3R8  33 OHM  [MX_R0402_SMALL_T01]  48.21 65.95 0 top
F3R9  33 OHM  [MX_R0402_SMALL_T01]  64.54 66.59 180 top
F3R10  33 OHM  [MX_R0402_SMALL_T01]  65.25 72.38 180 top
F3R11  33 OHM  [MX_R0402_SMALL_T01]  64.72 71.36 0 top
F3R12  33 OHM  [MX_R0402_SMALL_T01]  47.55 70.53 0 top
F3R20  0Ohm  [MX_R0402_SHORT_SMALL_T01]  44.68 67.22 180 top
F3R21  0Ohm  [MX_R0402_SHORT_SMALL_T01]  44.68 69.59 180 top
F3R22  0 Ohm  [MX_R0402_SMALL_T01]  64.57 67.6 180 top
F3R23  1.5K  [MX_R0402_SMALL_T01]  65.63 73.4 180 top
F3R24  0Ohm  [MX_R0402_SHORT_SMALL_T01]  44.68 66.23 180 top
F3R25  0Ohm  [MX_R0402_SHORT_SMALL_T01]  44.68 68.19 180 top
F3R26  0Ohm  [MX_R0402_SHORT_SMALL_T01]  44.68 70.5 180 top
F3R27  0Ohm  [MX_R0402_SHORT_SMALL_T01]  44.68 64.2 180 top
F3R28  0Ohm  [MX_R0402_SHORT_SMALL_T01]  52.02 108.96 0 top
F3R29  0Ohm  [MX_R0402_SHORT_SMALL_T01]  39.11 76.39 180 top
F3R70  0  [MX_R0402_SMALL_T01]  17.55 67.59 0 bottom
F3R71  2.2K  [MX_R0402_SMALL_T01]  66.66 64.79 270 top
FCB1  10PF/50V  [MX_C0402_SMALL_T01]  167.11 75.91 0 top
FCB2  10PF/50V  [MX_C0402_SMALL_T01]  160.09 71.06 90 bottom
FD1  BAT54CW  [MX_SOT323]  160.08 68.25 270 bottom
FR1  4.7KOHM  [MX_R0402_SMALL_T01]  167.06 78.09 0 top
FR2  150 OHM  [MX_R0603_SMALL_T01]  167.09 77 0 top
FR10  8.2K  [MX_R0402_SMALL_T01]  6.92 99.84 0 top
FR12  8.2K  [MX_R0402_SMALL_T01]  125.7 158.23 90 top
H1  C315D181N  [HOLE_C315D181N_M2_P2_V8]  79.86 132.98 0 top
H2  C275D177N  [HOLE_C275D177N_M2_P2_V8]  43.95 26.3 180 top
H3  C334D157N  [HOLE_C334D157N_M2_P2_V8]  156.94 155.49 0 top
H4  C275D177N  [HOLE_C275D177N_M2_P2_V8]  12.95 32.23 0 top
H5  C315D181N  [HOLE_C315D181N_M2_P2_V8#2]  165.86 132.98 0 top
H6  C334D157N  [HOLE_C334D157N_M2_P2_V8]  6.35 138.98 0 top
H7  C275D177N  [HOLE_C275D177N_M2_P2_V8]  12.95 82.23 0 top
H8  C334D157N  [HOLE_C334D157N_M2_P2_V8]  165 17.3 0 top
H9  C394D157N  [HOLE_C394D157N_M2_P2_V8_SPE]  80.5 47.28 0 top
H10  D169N_D98x197N  [H_2D_D169ND98X197N_M2_P2_V7]  79.86 90.98 0 top
H11  C315D169N  [HOLE_C315D169N_M2_P2_V8]  165.86 90.98 0 top
H12  C157D157N  [HOLE_C157D157N]  91 10.3 0 top
H13  CT217B63D47  [MX_SMT_NUT_CT217B63D47_NSP]  29.45 42.25 0 top
H14  CT217B63D47  [MX_SMT_NUT_CT217B63D47_NSP]  58.45 40.25 0 top
H15  O118X28DO118X28N  [A_HOLE_O118X28DO118X28N]  61.44 49.16 90 top
H16  O118X28DO118X28N  [A_HOLE_O118X28DO118X28N]  54.22 18.74 0 top
HC1  0.022UF/16V  [MX_C0402_SMALL_T01]  150.17 81.28 180 top
HC2  0.022UF/16V  [MX_C0402_SMALL_T01]  150.22 78.74 0 top
HC3  0.1UF/16V  [MX_C0402_SMALL_T01]  87.21 135.36 90 top
HC4  22UF/6.3V  [MX_C0603_SMALL_T02]  85.66 123.31 90 top
HC5  1UF/6.3V  [MX_C0402_SMALL_T01]  86.88 123.87 90 top
HC6  1000PF/50V  [MX_C0402_SMALL_T01]  166.85 49.37 0 bottom
HC7  1000PF/50V  [MX_C0402_SMALL_T01]  165.05 49.37 180 bottom
HC11  22UF/6.3V  [MX_C0603_SMALL_T02]  57.57 108.23 180 bottom
HC12  22UF/6.3V  [MX_C0603_SMALL_T02]  57.57 106.91 180 bottom
HC13  22UF/6.3V  [MX_C0603_SMALL_T02]  60.03 94.67 90 bottom
HC14  1UF/6.3V  [TX_C0201_T009_H14]  55.32 89.2 180 bottom
HC15  1UF/6.3V  [TX_C0201_T009_H14]  33.73 76.32 0 top
HC16  1UF/6.3V  [TX_C0201_T009_H14]  50.55 94.81 90 bottom
HC17  1UF/6.3V  [TX_C0201_T009_H14]  53.56 88.84 90 bottom
HC18  1UF/6.3V  [TX_C0201_T009_H14]  51.22 89.22 90 bottom
HC19  22UF/6.3V  [MX_C0603_SMALL_T02]  62.71 81.6 0 bottom
HC20  22UF/6.3V  [MX_C0603_SMALL_T02]  62.71 80.28 0 bottom
HC21  1UF/6.3V  [TX_C0201_T009_H14]  62.43 79.01 0 bottom
HC23  1UF/6.3V  [TX_C0201_T009_H14]  51.84 97.14 270 bottom
HC24  1UF/6.3V  [TX_C0201_T009_H14]  61.9 105.76 270 bottom
HC25  1UF/6.3V  [TX_C0201_T009_H14]  53.77 94.57 90 bottom
HC26  1UF/6.3V  [TX_C0201_T009_H14]  61.01 105.76 270 bottom
HC27  1UF/6.3V  [TX_C0201_T009_H14]  50.55 93.13 90 bottom
HC28  1UF/6.3V  [TX_C0201_T009_H14]  50.9 97.14 270 bottom
HC29  1UF/6.3V  [TX_C0201_T009_H14]  51.58 90.87 270 bottom
HC30  1000PF/50V  [MX_C0402_SMALL_T01]  134.52 120.34 90 bottom
HC31  1000PF/50V  [MX_C0402_SMALL_T01]  110.64 117.46 0 bottom
HCB3  0.1UF/16V  [MX_C0402_SMALL_T01]  72.3 109.86 0 top
HCB4  0.1UF/6.3V  [TX_C0201]  10.52 45.31 270 bottom
HCB5  0.1UF/16V  [MX_C0402_SMALL_T01]  82.27 104.84 180 bottom
HCB6  0.1UF/16V  [MX_C0402_SMALL_T01]  78.46 112.44 180 top
HEATSINK  HEATSINK_2ANCHOR  [HSK_4P_1071X1071_2ANCHO_LF5]  51.58 92.45 90 top
HQ1  LMBT3904LT1G  [TX_SOT23_2D4_122X55_H44]  152.94 75.57 180 top
HQ2  LMBT3904LT1G  [TX_SOT23_2D4_122X55_H44]  154.8 80.39 270 top
HR1  10K  [MX_R0402_SMALL_T01]  156.1 75.03 270 top
HR2  4.7K  [MX_R0402_SMALL_T01]  157.32 79.48 270 top
HR3  0Ohm  [MX_R0402_SHORT_SMALL_T01]  155.56 78.23 180 top
HR4  1.2K  [MX_R0402_SMALL_T01]  153.91 78.23 0 top
HR5  2  [MX_R0603_SMALL_T01]  148.27 79.96 180 top
HR6  2  [MX_R0603_SMALL_T01]  148.32 78.74 180 top
HR7  24.9  [MX_R0402_SMALL_T01]  148.52 81.02 180 top
HR8  24.9  [MX_R0402_SMALL_T01]  150.22 77.75 180 top
HR9  24.9  [MX_R0402_SMALL_T01]  111.39 119.47 90 bottom
HR10  24.9  [MX_R0402_SMALL_T01]  112.35 119.48 90 bottom
HR12  1K  [MX_R0402_SMALL_T01]  134.6 105.53 90 bottom
HR14  100  [MX_R0402_SMALL_T01]  135.69 118.61 90 bottom
HR15  56  [MX_R0402_SMALL_T01]  135.65 116.96 90 bottom
HR23  220  [MX_R0402_SMALL_T01]  134.73 116.96 270 bottom
HR24  0Ohm  [MX_R0402_SHORT_SMALL_T01]  86.93 133.17 180 top
HR25  20  [MX_R0402_SMALL_T01]  86.89 129.91 270 top
HR29  1K  [MX_R0402_SMALL_T01]  133.08 120.67 0 bottom
HR30  1K  [MX_R0402_SMALL_T01]  86.52 137.03 0 top
HR32  0  [MX_R0402_SMALL_T01]  86.95 131.5 0 top
HR33  499  [MX_R0402_SMALL_T01]  134.52 118.71 90 bottom
HR34  20  [MX_R0402_SMALL_T01]  86.93 134.08 0 top
HR35  20  [MX_R0402_SMALL_T01]  110.42 118.74 270 bottom
HR36  1KOhm  [MX_R0402_SMALL_T01]  80.87 119.8 180 bottom
HR37  1KOhm  [MX_R0402_SMALL_T01]  80.87 118.73 180 bottom
HR38  1KOhm  [MX_R0402_SMALL_T01]  80.87 117.82 0 bottom
HR39  1KOhm  [MX_R0402_SMALL_T01]  80.87 116.83 180 bottom
HR40  1KOhm  [MX_R0402_SMALL_T01]  80.87 115.43 180 bottom
HR41  1KOhm  [MX_R0402_SMALL_T01]  80.87 114.39 180 bottom
HR42  1KOhm  [MX_R0402_SMALL_T01]  80.87 113.46 180 bottom
HR43  1KOhm  [MX_R0402_SMALL_T01]  80.87 112.41 180 bottom
HR44  1KOhm  [MX_R0402_SMALL_T01]  73.1 118.79 180 top
HR45  1KOhm  [MX_R0402_SMALL_T01]  73.11 117.83 180 top
HR46  1KOhm  [MX_R0402_SMALL_T01]  73.11 116.9 180 top
HR47  1KOhm  [MX_R0402_SMALL_T01]  73.11 115.99 180 top
HR48  1KOhm  [MX_R0402_SMALL_T01]  71.5 112.86 180 top
HR49  1KOhm  [MX_R0402_SMALL_T01]  71.5 113.78 180 top
HR54  1KOhm  [MX_R0402_SMALL_T01]  71.5 111.94 180 top
HR55  1KOhm  [MX_R0402_SMALL_T01]  71.5 111.02 180 top
HR57  49.9  [MX_R0402_SMALL_T01]  114.61 117.5 0 top
HR58  0  [MX_R0402_SMALL_T01]  85.11 121.4 90 top
HR59  0Ohm  [MX_R0603_SHORT_SMALL_T01]  44.25 93.94 270 bottom
HR61  0Ohm  [MX_R0603_SHORT_SMALL_T01]  52.38 69.29 180 bottom
HR63  0Ohm  [MX_R0402_SHORT_SMALL_T01]  113.58 105.47 180 bottom
HR64  0  [MX_R0402_SMALL_T01]  112.11 107.12 180 bottom
HR66  0Ohm  [MX_R0603_SHORT_SMALL_T01]  47.37 94.35 0 bottom
HR67  0Ohm  [MX_R0603_SHORT_SMALL_T01]  35.84 100.54 90 bottom
HR69  4.7K  [MX_R0402_SMALL_T01]  19.69 15.97 0 top
HR70  4.7K  [MX_R0402_SMALL_T01]  18.2 17.85 90 bottom
HR72  0  [MX_R0603_SMALL_T01]  45.48 93.94 270 bottom
HR73  0Ohm  [MX_R0603_SHORT_SMALL_T01]  34.8 103.16 90 bottom
HR74  0Ohm  [MX_R0603_SMALL_T01]  45.36 89.68 0 bottom
HR81  51 OHM  [MX_R0402_SMALL_T01]  83.74 124.5 0 top
HR82  1KOhm  [MX_R0402_SMALL_T01]  73.11 115.07 180 top
HR83  1KOhm  [MX_R0402_SMALL_T01]  73.07 119.75 180 top
HR84  1KOhm  [MX_R0402_SMALL_T01]  73.11 114.12 180 top
HR85  1KOhm  [MX_R0402_SMALL_T01]  71.27 114.82 0 top
HR91  100  [MX_R0402_SMALL_T01]  83.68 122.76 180 bottom
HR93  1KOhm  [MX_R0402_SMALL_T01]  80.87 110.58 180 bottom
HR96  0  [MX_R0402_SMALL_T01]  78.46 113.38 180 top
HR98  0  [MX_R0402_SMALL_T01]  82.27 103.9 0 bottom
HR343  0  [MX_R0402_SMALL_T01]  86.28 135.36 90 top
HR346  0  [MX_R0402_SMALL_T01]  81.02 123.48 0 bottom
HR347  51 OHM  [MX_R0402_SMALL_T01]  80.87 120.72 180 bottom
HR364  1.5K  [MX_R0402_SMALL_T01]  78.59 116.66 180 top
HR365  150 Ohm  [MX_R0402_SMALL_T01]  78.59 115.72 0 top
HR366  0  [MX_R0402_SMALL_T01]  40.05 111.27 180 top
HR367  0  [MX_R0402_SMALL_T01]  86.38 126.75 0 bottom
HR368  0Ohm  [MX_R0402_SHORT_SMALL_T01]  44.39 109.28 90 top
HR369  0Ohm  [MX_R0402_SHORT_SMALL_T01]  43.25 108.57 90 bottom
HR370  0Ohm  [MX_R0402_SHORT_SMALL_T01]  79.35 104.56 270 bottom
HR371  0  [MX_R0402_SMALL_T01]  80.03 120.74 180 top
HR372  0  [MX_R0402_SMALL_T01]  84.77 124.28 180 bottom
HR373  0  [MX_R0402_SMALL_T01]  45.3 108.65 90 top
HR374  1KOhm  [MX_R0402_SMALL_T01]  80.87 109.67 180 bottom
HR377  0  [MX_R0402_SMALL_T01]  87.03 123.97 0 bottom
HR378  1KOhm  [MX_R0402_SMALL_T01]  87.03 123.06 180 bottom
HR379  1K  [MX_R0402_SMALL_T01]  78.48 114.37 180 top
HR380  0  [MX_R0402_SMALL_T01]  72.3 108.01 180 top
HR381  0Ohm  [MX_R0402_SHORT_SMALL_T01]  80.64 103.93 180 bottom
HR383  0  [MX_R0402_SMALL_T01]  84.87 125.19 0 bottom
HR384  0  [MX_R0402_SMALL_T01]  81.41 120.26 270 top
HR385  1.5K  [MX_R0402_SMALL_T01]  81.02 124.45 180 bottom
HR392  1KOhm  [MX_R0402_SMALL_T01]  80.87 111.5 180 bottom
HR399  1KOhm  [MX_R0402_SMALL_T01]  72.3 108.92 0 top
HR410  0  [MX_R0402_SMALL_T01]  42.31 108.57 90 bottom
HR411  0Ohm  [MX_R0402_SHORT_SMALL_T01]  131.33 59.89 180 bottom
HR413  0Ohm  [MX_R0402_SHORT_SMALL_T01]  86.94 125.18 0 top
HR422  0Ohm  [MX_R0603_SHORT_SMALL_T01]  65.91 81.8 270 top
HR423  0Ohm  [MX_R0603_SHORT_SMALL_T01]  57.57 109.5 0 bottom
HR424  0  [MX_R0603_SMALL_T01]  46.71 92.47 90 bottom
HR425  0Ohm  [MX_R0603_SHORT_SMALL_T01]  39.09 99.1 0 bottom
HR426  0  [MX_R0402_SMALL_T01]  81.5 114.4 180 top
HR427  0  [MX_R0402_SMALL_T01]  81.49 115.32 0 top
HT1  TPC26T  [MX_TPC26T_S4_68]  147.33 84.4 180 bottom
HT2  TPC26T  [MX_TPC26T_S4_68]  88.72 141.21 180 bottom
HT3  TPC26T  [MX_TPC26T_S4_68]  159.1 104.76 90 bottom
HT4  TPC26T  [MX_TPC26T_S4_68]  86.64 140.96 180 bottom
HT5  TPC26T  [MX_TPC26T_S4_68]  97.36 137.78 180 bottom
HT6  TPC26T  [MX_TPC26T_S4_68]  91.46 136.64 180 bottom
HT7  TPC26T  [MX_TPC26T_S4_68]  88.27 133.4 180 bottom
HT8  TPC26T  [MX_TPC26T_S4_68]  92.25 142.38 180 bottom
HT9  TPC26T  [MX_TPC26T_S4_68]  91.77 75.78 180 bottom
HT10  TPC26T  [MX_TPC26T_S4_68]  116.1 117.21 180 bottom
HT11  TPC26T  [MX_TPC26T_S4_68]  91.26 73.95 180 bottom
HT12  TPC26T  [MX_TPC26T_S4_68]  91.26 139.16 180 bottom
HT13  TPC26T  [MX_TPC26T_S4_68]  89.43 139.46 180 bottom
HT14  TPC26T  [MX_TPC26T_S4_68]  90.14 142.61 90 bottom
HT15  TPC26T  [MX_TPC26T_S4_68]  93.37 138.39 180 bottom
HT16  TPC26T  [MX_TPC26T_S4_68]  113.41 119.32 180 bottom
HT17  TPC26T  [MX_TPC26T_S4_68]  117.75 119.88 180 bottom
HT18  TPC26T  [MX_TPC26T_S4_68]  149.92 84.05 90 bottom
HT20  TPC26T  [MX_TPC26T_S4_68]  147.37 144.44 180 bottom
HT22  TPC26T  [MX_TPC26T_S4_68]  157.77 105.97 180 bottom
HT26  TPC26T  [MX_TPC26T_S4_68]  95.63 138.01 90 bottom
HT27  TPC26T  [MX_TPC26T_S4_68]  116 119.01 180 bottom
HT28  TPC26T  [MX_TPC26T_S4_68]  119.58 120.26 180 bottom
HT29  TPC26T  [MX_TPC26T_S4_68]  90.04 137.81 180 bottom
HT30  TPC26T  [MX_TPC26T_S4_68]  117.57 118.12 180 bottom
HT31  TPC26T  [MX_TPC26T_S4_68]  115.7 120.72 180 bottom
HT32  TPC26T  [MX_TPC26T_S4_68]  90.47 140.88 180 bottom
HT33  TPC26T  [MX_TPC26T_S4_68]  148.56 143.16 180 bottom
HT34  TPC26T  [MX_TPC26T_S4_68]  111.89 108.04 180 bottom
HT37  TPC26T  [MX_TPC26T_S4_68]  126.21 105.17 180 bottom
HT38  TPC26T  [MX_TPC26T_S4_68]  157.43 104.05 180 bottom
HT39  TPC26T  [MX_TPC26T_S4_68]  110.31 108.8 180 bottom
HT40  TPC26T  [MX_TPC26T_S4_68]  92.35 140.6 180 bottom
HT41  TPC26T  [MX_TPC26T_S4_68]  166.85 157.85 180 bottom
HT42  TPC26T  [MX_TPC26T_S4_68]  164.39 159.3 180 bottom
HT43  TPC26T  [MX_TPC26T_S4_68]  165.02 157.65 180 bottom
HT44  TPC26T  [MX_TPC26T_S4_68]  166.27 159.5 180 bottom
HT45  TPC26T  [MX_TPC26T_S4_68]  163.75 159.61 0 top
HT46  TPC26T  [MX_TPC26T_S4_68]  70.89 44.13 180 bottom
HT47  TPC26T  [MX_TPC26T_S4_68]  72.74 62.5 180 bottom
HT48  TPC26T  [MX_TPC26T_S4_68]  65.91 69.97 180 bottom
HT49  TPC26T  [MX_TPC26T_S4_68]  64.44 70.91 180 bottom
HT50  TPC26T  [MX_TPC26T_S4_68]  72.51 43.17 180 bottom
HT51  TPC26T  [MX_TPC26T_S4_68]  65.2 152.62 0 top
HT52  TPC26T  [MX_TPC26T_S4_68]  61.7 150.74 0 top
HT53  TPC26T  [MX_TPC26T_S4_68]  63.22 152.03 0 top
HT54  TPC26T  [MX_TPC26T_S4_68]  61.8 148.88 0 top
HT55  TPC26T  [MX_TPC26T_S4_68]  63.27 153.99 0 top
HT56  TPC26T  [MX_TPC26T_S4_68]  58.24 139.56 180 bottom
HT57  TPC26T  [MX_TPC26T_S4_68]  54.28 139.56 180 bottom
HT58  TPC26T  [MX_TPC26T_S4_68]  50.64 138.01 180 bottom
HT59  TPC26T  [MX_TPC26T_S4_68]  47.41 140.56 180 bottom
HT60  TPC26T  [MX_TPC26T_S4_68]  56.26 139.56 180 bottom
HT61  TPC26T  [MX_TPC26T_S4_68]  62.46 42.66 180 bottom
HT62  TPC26T  [MX_TPC26T_S4_68]  59.97 42.66 180 bottom
HT63  TPC26T  [MX_TPC26T_S4_68]  57.48 42.66 180 bottom
HT64  TPC26T  [MX_TPC26T_S4_68]  61.29 44.29 180 bottom
HT65  TPC26T  [MX_TPC26T_S4_68]  58.29 44.29 180 bottom
HT66  TPC26T  [MX_TPC26T_S4_68]  108.15 139.1 180 bottom
HT67  TPC26T  [MX_TPC26T_S4_68]  115.9 139.1 180 bottom
HT68  TPC26T  [MX_TPC26T_S4_68]  117.85 139.1 180 bottom
HT69  TPC26T  [MX_TPC26T_S4_68]  117.37 141.03 180 bottom
HT70  TPC26T  [MX_TPC26T_S4_68]  114.6 141.03 180 bottom
HT71  TPC26T  [MX_TPC26T_S4_68]  112.32 141.09 180 bottom
HT72  TPC26T  [MX_TPC26T_S4_68]  109.93 141.03 180 bottom
HT73  TPC26T  [MX_TPC26T_S4_68]  107.44 141.03 180 bottom
HT74  TPC26T  [MX_TPC26T_S4_68]  110.64 139.1 180 bottom
HT75  TPC26T  [MX_TPC26T_S4_68]  113.36 139.1 180 bottom
HT76  TPC26T  [MX_TPC26T_S4_68]  83.54 36.39 180 bottom
HT77  TPC26T  [MX_TPC26T_S4_68]  125.25 110.86 180 bottom
HT78  TPC26T  [MX_TPC26T_S4_68]  162.36 103.34 180 bottom
HT79  TPC26T  [MX_TPC26T_S4_68]  77.34 73.98 0 top
HT80  TPC26T  [MX_TPC26T_S4_68]  134.54 72.56 0 top
HT81  TPC26T  [MX_TPC26T_S4_68]  137.39 72.56 0 top
HT82  TPC26T  [MX_TPC26T_S4_68]  114.86 109.44 180 bottom
HT83  TPC26T  [MX_TPC26T_S4_68]  75.82 76.16 0 top
J1  DC_PWR_JACK_9P  [MX_PWR_JACK_9P_2HD_FOX_LF5]  162.35 170.3 180 top
J8  LAN_JACK_12P  [MX_LAN_JACK_12P_2H_ALL_SMT]  26.11 164.58 180 top
J12  USB_CON_2X9P  [MX_USB_2X9P_4HD_RA_F71_LF5]  71.12 163.83 180 top
J13  USB_CON_2X4P  [MX_USB_2X4P_4HD_AMCOTE_LF5]  51.62 163.41 180 top
J68  WTOB_CON_24P  [MX_WTOB_24P_39_2HD_ACES]  80.19 146.65 90 top
J69  WTOB_CON_30P  [MX_WTOB_30P_20_6HD_STARCONN]  56.58 143.37 90 top
J89  PHONE_JACK_6P  [MX_PHONE_JACK_6P_2H_COL_LF5]  40.47 3.55 0 top
J125  HDMI_CON_19P  [MX_HDMI_19P_59_5HD_LOT_LF5]  144.19 168.9 180 top
J133  USB_CON_9P  [MX_USB_9P_2HOLD_RA_JCTC_LF5]  78.8 11.78 0 top
J200  USB_CON_9P  [MX_USB_9P_2HOLD_RA_JCTC_LF5]  58.8 11.78 0 top
J218  MINI_PCI_67P  [MX_MIN_PCI_67P_20_4H]  43.95 54.55 0 top
J219  MINI_PCI_67P  [MX_MINI_PCI_67P_20_4H_LOTE1]  12.94 110.48 0 top
J301  PHONE_JACK_6P  [T_PHONE_JACK_6P_4H_SING_LF5]  29.8 5.25 0 top
J302  DISPLAY_CON_20P  [MX_DISPLAY_20P_4H_COXOC_LF5]  122.01 168.33 180 top
J303  HEADER_2X4P  [MX_HD_2X4P_50_SINYA]  70.25 59.38 0 top
JMP1  HEADER_2X3P  [MX_HD_2X3P_100_LF3]  49.82 150.47 270 top
JP1  -  [SHORTPIN]  27.74 118.63 270 top
JP2801  ANCHOR_2P  [MX_ANCHOR_2P_100_AMCO_LF5]  68.83 115.33 270 top
JP2802  ANCHOR_2P  [MX_ANCHOR_2P_100_AMCO_LF5]  34.33 69.57 270 top
L8  180OHM/100MHz/300mA  [MX_CHOKE_4P_79X47]  30.92 55.76 90 top
L16  120Ohm  [MX_L0402_SMALL_T01]  24.78 21.59 270 top
L21  70Ohm/100Mhz  [MX_L0603_SMALL_T02]  31.01 13.71 180 top
L22  70Ohm/100Mhz  [MX_L0603_SMALL_T02]  37.09 15.47 0 top
L82  70Ohm/100Mhz  [MX_L0603_SMALL_T02]  48.21 135.19 0 bottom
L117  70Ohm/100Mhz  [MX_L0603]  22.95 27.05 270 top
L120  120Ohm  [MX_L0402]  21.7 29.44 270 top
L122  70Ohm/100Mhz  [MX_L0603_SMALL_T02]  42.72 13.73 270 top
L123  70Ohm/100Mhz  [MX_L0603_SMALL_T02]  41.32 15.69 270 top
L129  120Ohm  [MX_L0402_SMALL_T01]  7.6 16.01 0 top
L4000  4.7UH/1.7A  [MX_CHOKE_2P_158X177]  21.63 143.53 270 top
L93006  70Ohm/100Mhz  [MX_L0603_SMALL_T02]  111.24 42.41 270 bottom
LC3  0.1UF/16V  [MX_C0402_SMALL_T01]  2.77 149.62 180 bottom
LC4  1000PF/2KV  [MX_C1206_H75]  3.07 165.24 0 bottom
LC5  0.1UF/16V  [MX_C0402_SMALL_T01]  17.09 150.54 270 top
LC6  470PF/50V  [MX_C0402_SMALL_T01]  14.32 146.7 90 bottom
LC7  0.1UF/16V  [MX_C0402_SMALL_T01]  26.85 150.76 180 top
LC8  0.1UF/16V  [MX_C0402_SMALL_T01]  36.47 156.58 90 top
LC9  1UF/6.3V  [TX_C0201_T009_H14]  2.79 150.56 180 bottom
LR9  680Ohm  [MX_R0402_SMALL_T01]  13.41 146.7 270 bottom
LR10  680Ohm  [MX_R0402_SMALL_T01]  37.41 156.58 270 top
LR11  120  [MX_R0402_SMALL_T01]  38.48 157.72 90 top
LT9  TPC26T  [MX_TPC26T_S4_68]  37.21 97.54 180 bottom
LT11  TPC26T  [MX_TPC26T_S4_68]  33.73 94.5 90 bottom
LT12  TPC26T  [MX_TPC26T_S4_68]  42.34 93.21 90 bottom
LU3  GST5009BMLF  [MX_TRANS_24P_39_595X394_DEL]  8.71 151.04 0 top
M1C43  0.1UF/16V  [MX_C0402_SMALL_T01]  122.39 36.84 0 bottom
M1C44  0.1UF/16V  [MX_C0402_SMALL_T01]  128.05 40.94 90 bottom
M1C49  0.1UF/16V  [MX_C0402_SMALL_T01]  31.32 51.55 270 top
M1C50  0.1UF/16V  [MX_C0402_SMALL_T01]  31.34 48.5 90 top
M1C51  0.1UF/16V  [MX_C0402_SMALL_T01]  56.83 52.69 180 top
M1C52  0.1UF/16V  [MX_C0402_SMALL_T01]  56.84 53.62 180 top
M1C66  0.1UF/16V  [MX_C0402_SMALL_T01]  12.4 57.88 90 bottom
M1C67  0.1UF/16V  [MX_C0402_SMALL_T01]  9.46 57.91 270 bottom
M1C69  0.1UF/16V  [MX_C0402_SMALL_T01]  50.67 57.22 180 bottom
M1C70  0.1UF/16V  [MX_C0402_SMALL_T01]  50.67 56.3 180 bottom
M1C73  0.1UF/16V  [MX_C0402_SMALL_T01]  153.19 162.42 270 top
M1C79  0.1UF/16V  [MX_C0402_SMALL_T01]  65.35 150.7 180 bottom
M1C80  0.1UF/16V  [MX_C0402_SMALL_T01]  61.52 151.63 180 bottom
M1C82  0.1UF/16V  [MX_C0402_SMALL_T01]  39.75 161.61 180 top
M1C83  0.1UF/16V  [MX_C0402_SMALL_T01]  41.32 170.17 90 top
M1C88  0.1UF/16V  [MX_C0402_SMALL_T01]  73.56 151.63 180 bottom
M1C89  0.1UF/16V  [MX_C0402_SMALL_T01]  82.94 151.86 0 bottom
M1C96  0.1UF/16V  [MX_C0402_SMALL_T01]  96.86 23.6 90 bottom
M1C97  0.1UF/16V  [MX_C0402_SMALL_T01]  98.31 27.84 90 bottom
M1C99  0.1UF/16V  [MX_C0402_SMALL_T01]  99.9 11.57 180 bottom
M1C100  0.1UF/16V  [MX_C0402_SMALL_T01]  111.82 163.84 90 top
M1C101  0.1UF/16V  [MX_C0402_SMALL_T01]  103.78 170.17 180 bottom
M1C102  0.1UF/16V  [MX_C0402_SMALL_T01]  111.3 168.52 270 top
M1C103  0.1UF/16V  [MX_C0402_SMALL_T01]  116.2 157.36 270 top
M1C104  0.1UF/16V  [MX_C0402_SMALL_T01]  117.12 157.36 270 top
M1C105  0.1UF/16V  [MX_C0402_SMALL_T01]  115.14 157.36 270 top
M1C106  0.1UF/16V  [MX_C0402_SMALL_T01]  114.22 157.36 270 top
M1C107  0.1UF/16V  [MX_C0402_SMALL_T01]  118.44 157.36 270 top
M1C108  0.1UF/16V  [MX_C0402_SMALL_T01]  119.35 157.36 270 top
M1C109  0.1UF/16V  [MX_C0402_SMALL_T01]  121.41 157.36 270 top
M1C110  0.1UF/16V  [MX_C0402_SMALL_T01]  120.5 157.36 270 top
M1C111  0.1UF/16V  [MX_C0402_SMALL_T01]  103.76 168.9 180 bottom
M1C112  0.1UF/16V  [MX_C0402_SMALL_T01]  111.08 160.94 180 top
M1C113  0.1UF/16V  [MX_C0402_SMALL_T01]  124.31 158.94 180 top
M1C114  0.1UF/16V  [MX_C0402_SMALL_T01]  112.67 157.5 0 top
M1C115  0.1UF/16V  [MX_C0402_SMALL_T01]  73.94 17.16 0 top
M1C116  0.1UF/16V  [MX_C0402_SMALL_T01]  75.31 26.81 0 top
M1C117  0.1UF/16V  [MX_C0402_SMALL_T01]  139.22 156.96 90 top
M1C118  0.1UF/16V  [MX_C0402_SMALL_T01]  140.13 156.96 90 top
M1C119  0.1UF/16V  [MX_C0402_SMALL_T01]  135.56 157.67 90 top
M1C120  0.1UF/16V  [MX_C0402_SMALL_T01]  134.64 157.67 90 top
M1C121  0.1UF/16V  [MX_C0402_SMALL_T01]  141.16 156.96 90 top
M1C122  0.1UF/16V  [MX_C0402_SMALL_T01]  142.07 156.96 90 top
M1C123  0.1UF/16V  [MX_C0402_SMALL_T01]  132.61 157.67 90 top
M1C124  0.1UF/16V  [MX_C0402_SMALL_T01]  131.7 157.67 90 top
M1F2  1.1A/6V  [MX_POLYSWITCH_2P_0805_H30]  107.67 164.58 0 top
M1Q7  NTR4003NT1G  [MX_SOT23_2D4_122X55_H44]  151.16 159.82 270 top
M1Q8  NTR4003NT1G  [MX_SOT23_2D4_122X55_H44]  128.51 158.24 90 top
M1Q9  NX7002AK  [TX_SOT23_2D4_T01_H43]  137.06 159.25 180 top
M1R10  100K  [MX_R0402_SMALL_T01]  46.56 100.06 270 bottom
M1R14  20K  [MX_R0402_SMALL_T01]  153.44 160.95 180 top
M1R15  20K  [MX_R0402_SMALL_T01]  39.55 92.65 0 bottom
M1R16  100K  [MX_R0402_SMALL_T01]  35.89 112.97 270 bottom
M1R19  100K  [MX_R0402_SMALL_T01]  130.25 156.25 180 top
M1R20  100K  [MX_R0402_SMALL_T01]  126.47 159.5 180 top
M1R21  100K  [MX_R0402_SMALL_T01]  111.44 165.12 180 top
M1R22  100K  [MX_R0402_SMALL_T01]  111.41 166.29 0 top
M1R23  2.2K  [MX_R0402_SMALL_T01]  147.84 157.53 0 top
M1R24  2.2K  [MX_R0402_SMALL_T01]  146.21 157.53 180 top
M1R25  2.2KOHM  [MX_R0402_SMALL_T01]  147.79 161.04 180 top
M1R26  2.2KOHM  [MX_R0402_SMALL_T01]  146.11 161.04 0 top
M1U3  IP4284CZ10-TB  [MX_ESD_10P_20_98X39_NXP]  115.58 159.1 180 top
M1U4  IP4284CZ10-TB  [MX_ESD_10P_20_98X39_NXP]  120.76 159.25 0 top
M2R1  100  [MX_R0402_SMALL_T01]  150.57 156.61 0 top
MC5401  0.1UF/16V  [MX_C0402_SMALL_T01]  14.48 14.32 90 bottom
MC5402  0.1UF/16V  [MX_C0402_SMALL_T01]  31.06 18.71 270 top
MC8301  0.1UF/16V  [MX_C0402_SMALL_T01]  20.19 20.59 0 bottom
MC8302  0.1UF/16V  [MX_C0402_SMALL_T01]  17.18 19.63 270 bottom
MC8303  0.1UF/16V  [MX_C0402_SMALL_T01]  46.43 9.12 180 top
MC8304  0.1UF/16V  [MX_C0402_SMALL_T01]  46.43 10.04 180 top
MC8305  0.1UF/16V  [MX_C0402_SMALL_T01]  35.03 18.67 270 bottom
MQ26  NX7002AK  [TX_SOT23_2D4_T01_H43]  64.21 50.89 180 top
MQ27  NX7002AK  [TX_SOT23_2D4_T01_H43]  84.94 143.63 90 bottom
MQ28  NX7002AK  [TX_SOT23_2D4_T01_H43]  76.43 144.72 0 bottom
MR5401  0Ohm  [MX_R0603_SHORT_SMALL_T01]  38.45 18.68 270 bottom
MR5402  0Ohm  [MX_R0603_SHORT_SMALL_T01]  45.58 16.77 180 top
MR5403  0Ohm  [MX_R0603_SHORT_SMALL_T01]  37.13 18.68 270 bottom
NOREF  -  []  34.33 72.11 90 top
NOREF#2  -  []  44.17 156.11 90 top
NOREF#3  -  []  41.14 37.09 0 top
NOREF#4  -  []  113.29 39.97 0 top
NOREF#5  -  [unnamed#2]  -164.36 172.55 0 top
NOREF#6  -  [unnamed#3]  2.51 33.44 0 top
NOREF#7  -  []  53.76 68.46 0 top
NOREF#8  -  []  2.17 57.63 90 top
NOREF#9  -  [unnamed#3]  13.31 164.02 0 top
NOREF#10  -  []  54.56 67.54 0 top
NOREF#11  -  []  107.97 39.99 0 top
NOREF#12  -  []  5.77 114.85 90 top
NOREF#13  -  []  9.19 176.6 0 top
NOREF#14  -  [unnamed#3]  154.53 11.78 0 top
NOREF#15  -  [unnamed#2]  -160.22 -4.78 0 top
NOREF#16  -  []  2.17 120.1 0 top
NOREF#17  -  []  68.19 128.91 0 top
NOREF#18  -  []  63.17 20 90 top
NOREF#19  -  []  115.56 33.76 0 top
NOREF#20  -  []  24.97 132.39 0 top
NOREF#21  -  []  105.51 39.97 0 top
NOREF#22  -  []  165.52 48.78 90 top
NOREF#23  -  []  108.04 30.3 0 top
NOREF#24  -  []  34.33 67.03 0 top
NOREF#25  -  [unnamed#2]  157.86 177.08 0 top
NOREF#26  -  []  64.82 20.47 0 top
NOREF#27  -  []  115.26 27.56 0 top
NOREF#28  -  []  29.27 173.71 0 top
NOREF#29  -  []  110.36 30.13 90 top
NOREF#30  -  []  137.06 22.77 0 top
NOREF#31  -  []  48.12 158.08 90 top
NOREF#32  -  []  97.69 33.9 0 top
NOREF#33  -  []  136.14 40.02 0 top
NOREF#34  -  []  144.82 72.93 0 top
NOREF#35  -  []  123.3 39.91 0 top
NOREF#36  -  []  1.89 89.09 90 top
NOREF#37  -  []  2.17 126.6 90 top
NOREF#38  -  []  128.21 40.14 0 top
NOREF#39  -  []  45.05 157.73 90 top
NOREF#40  -  []  106.16 28.14 0 top
NOREF#41  -  []  20.32 89.42 90 top
NOREF#42  -  []  45.05 163.41 0 top
NOREF#43  -  []  167.8 159.41 90 top
NOREF#44  -  []  2.17 125.6 90 top
NOREF#45  -  []  68.83 112.79 90 top
